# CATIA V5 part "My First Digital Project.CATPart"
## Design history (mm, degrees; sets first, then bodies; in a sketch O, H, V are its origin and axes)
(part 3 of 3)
Set68 "IFC Single Panel"
  Set69 "Construction Geometry"
    UdfFeature26 "Insertion Axis": UdfInputSpec1 {plane2lines}, UdfInputSpec3 Project20, UdfInputSpec4 Project21, UdfInputSpec5 Project22, UdfComponents Set72, UdfOutputs AxisSystem42
    AxisSystem39 "Insertion Axis Clone": origin (14674.5386, 9859.6746, 133.35), X (0.2658, 0.964, 0), Y (-0.964, 0.2658, 0), Z (0, 0, 1)
    AxisSystem40 "Lining Axis": origin (14637.8088, 9869.8004, 133.35), X (0.2658, 0.964, 0), Y (-0.964, 0.2658, 0), Z (0, 0, 1)
    AxisSystem41 "Panel Axis": origin (14673.4799, 9879.7271, 152.4), X (0.2658, 0.964, 0), Y (-0.964, 0.2658, 0), Z (0, 0, 1)
    UdfFeature27 "Middle": UdfInputSpec1 {pointcoord X 0, Y 0, Z 0, RefAxis AxisSystem40}, UdfInputSpec2 {pointcoord X 526.9992 {= `UdfFeature27.Window Width` /2}, Y 0, Z 0, RefAxis AxisSystem40}, UdfInputSpec3 {pointcoord X 1053.9984 {= `UdfFeature27.Window Width`}, Y 0, Z 0, RefAxis AxisSystem40}, UdfComponents Set73, UdfOutputs Point212
  Set70 "Window Lining"
    Sketch17 "Opening Contour" on edge [XY plane of AxisSystem40 | ZX plane of AxisSystem40], origin (14637.8088, 9869.8004, 133.35), H (0.2658, 0.964, 0), V (0, 0, 1)
      line L1 (0, 0) -> (1053.9984, 0)
      line L2 (1053.9984, 0) -> (1053.9984, 2324.1)
      line L3 (1053.9984, 2324.1) -> (0, 2324.1)
      line L4 (0, 2324.1) -> (0, 0)
      length L4 = 2324.1
      length L3 = 1053.9984
      horizontal: L1 H, L3 H
      vertical: L2 V, L4 V
    Body36 "Lining"
      Pad8: profile Sketch17, direction (0.964, -0.2658, 0), length 38.1, mirrored extent, thin wall 19.05
  Set71 "Window Panel"
    Body37 "Panel"
      UdfFeature28 "IFC Window Panel": UdfInputSpec10 edge [ZX plane of AxisSystem41 | YZ plane of AxisSystem41], UdfInputSpec1 {pointcoord X 1015.8984 {= `External.Rotate Axis Offset`}, Y 0, Z 0, RefPoint vertex [YZ plane of AxisSystem41 | ZX plane of AxisSystem41 | XY plane of AxisSystem41], RefAxis AxisSystem41}, UdfInputSpec3 edge [ZX plane of AxisSystem41 | YZ plane of AxisSystem41], UdfInputSpec4 {pointcoord X 0, Y 0, Z 1015.8984 {= `External.Rotate Axis Offset`}, RefPoint vertex [YZ plane of AxisSystem41 | ZX plane of AxisSystem41 | XY plane of AxisSystem41], RefAxis AxisSystem41}, UdfComponents a sketch, UdfInputSpec6 edge [XY plane of AxisSystem41 | ZX plane of AxisSystem41], UdfInputSpec7 {pointcoord X 0 {= `External.X Translate`}, Y 0, Z 0 {= `External.Z Translate`}, RefPoint vertex [YZ plane of AxisSystem41 | ZX plane of AxisSystem41 | XY plane of AxisSystem41], RefAxis AxisSystem41}, UdfInputSpec9 edge [XY plane of AxisSystem41 | ZX plane of AxisSystem41], OperationType "SideHungRightHand", Open Ratio 0
Set72 "Insertion Geometry"
  Plane19 "Construction Plane": type 2Lines
  Project20 "Insertion Point clone": Support Plane19
  Project21 "Insertion Line Clone": Support Plane19
  Project22 "Orientation Line Clone": Support Plane19
  Line84 "X Direction": type Normal, RefPoint Project20, RefSkin Plane19, Start 0, End 1
  AxisSystem42 "Insertion Axis": origin (14674.5386, 9859.6746, 133.35), X (0.2658, 0.964, 0), Y (-0.964, 0.2658, 0), Z (0, 0, 1)
Set73 "UDF Geometry"
  Point211 "Left": (0, 0, 0), in AxisSystem40
  Point212 "Middle": (526.9992 {= `UdfFeature27.Window Width` /2}, 0, 0), in AxisSystem40
  Point213 "Right": (1053.9984 {= `UdfFeature27.Window Width`}, 0, 0), in AxisSystem40
Set74 "UDF Geometry"
  Line85 "V Rotation Axis": type PtDir, RefPoint {point type Coord, X 1015.8984 {= `External.Rotate Axis Offset`}, Y 0, Z 0, RefPoint vertex [YZ plane of AxisSystem41 | ZX plane of AxisSystem41 | XY plane of AxisSystem41], RefAxis AxisSystem41}, Direction edge [ZX plane of AxisSystem41 | YZ plane of AxisSystem41], Start 0, End 304.8
  Line86 "H Rotation Axis": type PtDir, RefPoint {point type Coord, X 0, Y 0, Z 1015.8984 {= `External.Rotate Axis Offset`}, RefPoint vertex [YZ plane of AxisSystem41 | ZX plane of AxisSystem41 | XY plane of AxisSystem41], RefAxis AxisSystem41}, Direction edge [XY plane of AxisSystem41 | ZX plane of AxisSystem41], Start 0, End 304.8
  Point214 "Translate Point": (0 {= `External.X Translate`}, 0, 0 {= `External.Z Translate`}), relative to vertex [YZ plane of AxisSystem41 | ZX plane of AxisSystem41 | XY plane of AxisSystem41], in AxisSystem41
  Line87 "Trans X Axis": type PtDir, RefPoint Point214, Direction edge [XY plane of AxisSystem41 | ZX plane of AxisSystem41], Start 0, End 304.8
  Line88 "Trans ZAxis": type PtDir, RefPoint Point214, Direction edge [ZX plane of AxisSystem41 | YZ plane of AxisSystem41], Start 0, End 304.8
  Rotate29 "Rotate Horizontal Point": ToTransfor Point214, Axis Line86, Angle 0 {= `External.Open Angle`}
  Rotate30 "Rotate Horizontal Z Axis": ToTransfor Line88, Axis Line86, Angle 0 {= `External.Open Angle`}
  Rotate31 "Rotate Vertical Point": ToTransfor Point214, Axis Line85, Angle 0 {= `External.Open Angle`}
  Rotate32 "Rotate Vertical X Axis": ToTransfor Line87, Axis Line85, Angle 0 {= `External.Open Angle`}
  Line89 "X Direction": stored without definition
  Line90 "Z Direction": stored without definition
  Point215 "Origin": stored without definition
  Plane20: type Normal, Curve Line90, RefPoint Point215
  Line91 "Y Direction": type Angle, RefPoint Point215, Curve Line89, Support Plane20, Start 0, End 304.8, Angle 90
  AxisSystem43 "Window Open Axis": origin (14673.4799, 9879.7271, 152.4), X (0.2658, 0.964, 0), Y (-0.964, 0.2658, 0), Z (0, 0, 1)
Set75 "UDF Geometry"
  Point216 "B-L": (25.4 {= UdfFeature28.FrameThickness}, 0, 25.4 {= UdfFeature28.FrameThickness}), relative to vertex [YZ plane of UdfFeature28 | ZX plane of UdfFeature28 | XY plane of UdfFeature28], in 
  Point217 "B": (507.9492 {= `UdfFeature28.Panel Width` /2}, 0, 25.4 {= UdfFeature28.FrameThickness}), relative to vertex [YZ plane of UdfFeature28 | ZX plane of UdfFeature28 | XY plane of UdfFeature28], in 
  Point218 "B-R": (990.4984 {= `UdfFeature28.Panel Width` -UdfFeature28.FrameThickness}, 0, 25.4 {= UdfFeature28.FrameThickness}), relative to vertex [YZ plane of UdfFeature28 | ZX plane of UdfFeature28 | XY plane of UdfFeature28], in 
  Point219 "R": (990.4984 {= Point218.X}, 0, 1143 {= `UdfFeature28.Panel Height` /2}), relative to vertex [YZ plane of UdfFeature28 | ZX plane of UdfFeature28 | XY plane of UdfFeature28], in 
  Point220 "T-R": (990.4984 {= Point218.X}, 0, 2260.6 {= `UdfFeature28.Panel Height` -UdfFeature28.FrameThickness}), relative to vertex [YZ plane of UdfFeature28 | ZX plane of UdfFeature28 | XY plane of UdfFeature28], in 
  Point221 "T": (507.9492 {= Point217.X}, 0, 2260.6 {= Point220.Z}), relative to vertex [YZ plane of UdfFeature28 | ZX plane of UdfFeature28 | XY plane of UdfFeature28], in 
  Point222 "T-L": (25.4 {= Point216.X}, 0, 2260.6 {= Point220.Z}), relative to vertex [YZ plane of UdfFeature28 | ZX plane of UdfFeature28 | XY plane of UdfFeature28], in 
  Point223 "L": (25.4 {= Point216.X}, 0, 1143 {= Point219.Z}), relative to vertex [YZ plane of UdfFeature28 | ZX plane of UdfFeature28 | XY plane of UdfFeature28], in 
  Point224 "C": (507.9492 {= `UdfFeature28.Panel Width` /2}, 0, 1143 {= `UdfFeature28.Panel Height` /2}), relative to vertex [YZ plane of UdfFeature28 | ZX plane of UdfFeature28 | XY plane of UdfFeature28], in 
  Point225 "B2": (0, 0, 76.2), relative to Point217, in 
  Point226 "T2": (0, 0, -76.2), relative to Point221, in 
  Point227 "L2": (76.2, 0, 0), relative to Point223, in 
  Point228 "R2": (-76.2, 0, 0), relative to Point219, in 
  Point229 "L3": (-253.9746 {= -`UdfFeature28.Panel Width` /4}, 0, 0), relative to Point224, in 
  Point230 "R3": (253.9746 {= -Point229.X}, 0, 0), relative to Point224, in 
  Point231 "T3": (0, 0, 571.5 {= `UdfFeature28.Panel Height` /4}), relative to Point224, in 
  Point232 "B3": (0, 0, -571.5 {= - Point231.Z}), relative to Point224, in 
  LineCorner79 "Left": Elements (Point222; Point219; Point216)
  LineCorner80 "Right": Elements (Point220; Point223; Point218)
  LineCorner81 "Top": Elements (Point222; Point217; Point220)
  LineCorner82 "Bottom": Elements (Point216; Point221; Point218)
  Join36 "Left and Bottom": Elements (LineCorner79; LineCorner82)
  Join37 "Right and Bottom": Elements (LineCorner80; LineCorner82)
  LineCorner83 "Pivot H Top": Elements (Point227; Point223; Point221; Point219; Point228)
  LineCorner84 "Pivot H Bottom": Elements (Point223; Point217; Point219)
  Join38 "Pivot H": Elements (LineCorner83; LineCorner84)
  LineCorner85 "Pivot V Left": Elements (Point226; Point221; Point223; Point217; Point225)
  LineCorner86 "Pivot V Right": Elements (Point221; Point219; Point217)
  Join39 "Pivot V": Elements (LineCorner85; LineCorner86)
  Line92 "Sliding H": type PtPt, FirstPoint Point229, SecondPoint Point230
  Line93 "Sliding V": type PtPt, FirstPoint Point231, SecondPoint Point232
  Point233: (25.4 {= UdfFeature28.FrameThickness}, 0, 0), relative to Point216, in 
  Point234: (-25.4 {= -UdfFeature28.FrameThickness}, 0, 25.4 {= UdfFeature28.FrameThickness}), relative to Point218, in 
  Point235: (25.4 {= UdfFeature28.FrameThickness}, 0, -25.4 {= -UdfFeature28.FrameThickness}), relative to Point222, in 
  Point236: (-25.4 {= -UdfFeature28.FrameThickness}, 0, 0), relative to Point220, in 
  Point237: (0, 0, -25.4 {= -UdfFeature28.FrameThickness}), relative to Point220, in 
  Point238: (0, 0, 25.4 {= UdfFeature28.FrameThickness}), relative to Point216, in 
  LineCorner87 "Removable-1": Elements (Point222; Point236; Point234; Point238)
  LineCorner88 "Removable-2": Elements (Point235; Point237; Point218; Point233)
  Line94 "Removable-3": type PtPt, FirstPoint Point237, SecondPoint Point233
  Join40 "Removable": Elements (LineCorner87; LineCorner88; Line94)
  LineCorner89 "Fixed": Elements (Point222; Point220; Point218; Point216)
  DatumCurve8 "OperationSymbol"
Body38 "Opening Volume Body"
  GTCArcGeoOpnVolume9 "Opening Volume"
Set76 "IFC Single Panel"
  Set77 "Construction Geometry"
    UdfFeature29 "Insertion Axis": UdfInputSpec1 {plane2lines}, UdfInputSpec3 Project23, UdfInputSpec4 Project24, UdfInputSpec5 Project25, UdfComponents Set80, UdfOutputs AxisSystem47
    AxisSystem44 "Insertion Axis Clone": origin (14991.6842, 11036.8997, 133.35), X (0.1815, 0.9834, 0), Y (-0.9834, 0.1815, 0), Z (0, 0, 1)
    AxisSystem45 "Lining Axis": origin (14954.2167, 11043.8131, 133.35), X (0.1815, 0.9834, 0), Y (-0.9834, 0.1815, 0), Z (0, 0, 1)
    AxisSystem46 "Panel Axis": origin (14988.8963, 11056.7857, 152.4), X (0.1815, 0.9834, 0), Y (-0.9834, 0.1815, 0), Z (0, 0, 1)
    UdfFeature30 "Middle": UdfInputSpec1 {pointcoord X 0, Y 0, Z 0, RefAxis AxisSystem45}, UdfInputSpec2 {pointcoord X 526.9992 {= `UdfFeature30.Window Width` /2}, Y 0, Z 0, RefAxis AxisSystem45}, UdfInputSpec3 {pointcoord X 1053.9984 {= `UdfFeature30.Window Width`}, Y 0, Z 0, RefAxis AxisSystem45}, UdfComponents Set81, UdfOutputs Point240
  Set78 "Window Lining"
    Sketch18 "Opening Contour" on edge [XY plane of AxisSystem45 | ZX plane of AxisSystem45], origin (14954.2167, 11043.8131, 133.35), H (0.1815, 0.9834, 0), V (0, 0, 1)
      line L1 (0, 0) -> (1053.9984, 0)
      line L2 (1053.9984, 0) -> (1053.9984, 2324.1)
      line L3 (1053.9984, 2324.1) -> (0, 2324.1)
      line L4 (0, 2324.1) -> (0, 0)
      length L4 = 2324.1
      length L3 = 1053.9984
      horizontal: L1 H, L3 H
      vertical: L2 V, L4 V
    Body39 "Lining"
      Pad9: profile Sketch18, direction (0.9834, -0.1815, 0), length 38.1, mirrored extent, thin wall 19.05
  Set79 "Window Panel"
    Body40 "Panel"
      UdfFeature31 "IFC Window Panel": UdfInputSpec10 edge [ZX plane of AxisSystem46 | YZ plane of AxisSystem46], UdfInputSpec1 {pointcoord X 1015.8984 {= `External.Rotate Axis Offset`}, Y 0, Z 0, RefPoint vertex [YZ plane of AxisSystem46 | ZX plane of AxisSystem46 | XY plane of AxisSystem46], RefAxis AxisSystem46}, UdfInputSpec3 edge [ZX plane of AxisSystem46 | YZ plane of AxisSystem46], UdfInputSpec4 {pointcoord X 0, Y 0, Z 1015.8984 {= `External.Rotate Axis Offset`}, RefPoint vertex [YZ plane of AxisSystem46 | ZX plane of AxisSystem46 | XY plane of AxisSystem46], RefAxis AxisSystem46}, UdfComponents a sketch, UdfInputSpec6 edge [XY plane of AxisSystem46 | ZX plane of AxisSystem46], UdfInputSpec7 {pointcoord X 0 {= `External.X Translate`}, Y 0, Z 0 {= `External.Z Translate`}, RefPoint vertex [YZ plane of AxisSystem46 | ZX plane of AxisSystem46 | XY plane of AxisSystem46], RefAxis AxisSystem46}, UdfInputSpec9 edge [XY plane of AxisSystem46 | ZX plane of AxisSystem46], OperationType "SideHungRightHand", Open Ratio 0
Set80 "Insertion Geometry"
  Plane21 "Construction Plane": type 2Lines
  Project23 "Insertion Point clone": Support Plane21
  Project24 "Insertion Line Clone": Support Plane21
  Project25 "Orientation Line Clone": Support Plane21
  Line95 "X Direction": type Normal, RefPoint Project23, RefSkin Plane21, Start 0, End 1
  AxisSystem47 "Insertion Axis": origin (14991.6842, 11036.8997, 133.35), X (0.1815, 0.9834, 0), Y (-0.9834, 0.1815, 0), Z (0, 0, 1)
Set81 "UDF Geometry"
  Point239 "Left": (0, 0, 0), in AxisSystem45
  Point240 "Middle": (526.9992 {= `UdfFeature30.Window Width` /2}, 0, 0), in AxisSystem45
  Point241 "Right": (1053.9984 {= `UdfFeature30.Window Width`}, 0, 0), in AxisSystem45
Set82 "UDF Geometry"
  Line96 "V Rotation Axis": type PtDir, RefPoint {point type Coord, X 1015.8984 {= `External.Rotate Axis Offset`}, Y 0, Z 0, RefPoint vertex [YZ plane of AxisSystem46 | ZX plane of AxisSystem46 | XY plane of AxisSystem46], RefAxis AxisSystem46}, Direction edge [ZX plane of AxisSystem46 | YZ plane of AxisSystem46], Start 0, End 304.8
  Line97 "H Rotation Axis": type PtDir, RefPoint {point type Coord, X 0, Y 0, Z 1015.8984 {= `External.Rotate Axis Offset`}, RefPoint vertex [YZ plane of AxisSystem46 | ZX plane of AxisSystem46 | XY plane of AxisSystem46], RefAxis AxisSystem46}, Direction edge [XY plane of AxisSystem46 | ZX plane of AxisSystem46], Start 0, End 304.8
  Point242 "Translate Point": (0 {= `External.X Translate`}, 0, 0 {= `External.Z Translate`}), relative to vertex [YZ plane of AxisSystem46 | ZX plane of AxisSystem46 | XY plane of AxisSystem46], in AxisSystem46
  Line98 "Trans X Axis": type PtDir, RefPoint Point242, Direction edge [XY plane of AxisSystem46 | ZX plane of AxisSystem46], Start 0, End 304.8
  Line99 "Trans ZAxis": type PtDir, RefPoint Point242, Direction edge [ZX plane of AxisSystem46 | YZ plane of AxisSystem46], Start 0, End 304.8
  Rotate33 "Rotate Horizontal Point": ToTransfor Point242, Axis Line97, Angle 0 {= `External.Open Angle`}
  Rotate34 "Rotate Horizontal Z Axis": ToTransfor Line99, Axis Line97, Angle 0 {= `External.Open Angle`}
  Rotate35 "Rotate Vertical Point": ToTransfor Point242, Axis Line96, Angle 0 {= `External.Open Angle`}
  Rotate36 "Rotate Vertical X Axis": ToTransfor Line98, Axis Line96, Angle 0 {= `External.Open Angle`}
  Line100 "X Direction": stored without definition
  Line101 "Z Direction": stored without definition
  Point243 "Origin": stored without definition
  Plane22: type Normal, Curve Line101, RefPoint Point243
  Line102 "Y Direction": type Angle, RefPoint Point243, Curve Line100, Support Plane22, Start 0, End 304.8, Angle 90
  AxisSystem48 "Window Open Axis": origin (14988.8963, 11056.7857, 152.4), X (0.1815, 0.9834, 0), Y (-0.9834, 0.1815, 0), Z (0, 0, 1)
Set83 "UDF Geometry"
  Point244 "B-L": (25.4 {= UdfFeature31.FrameThickness}, 0, 25.4 {= UdfFeature31.FrameThickness}), relative to vertex [YZ plane of UdfFeature31 | ZX plane of UdfFeature31 | XY plane of UdfFeature31], in 
  Point245 "B": (507.9492 {= `UdfFeature31.Panel Width` /2}, 0, 25.4 {= UdfFeature31.FrameThickness}), relative to vertex [YZ plane of UdfFeature31 | ZX plane of UdfFeature31 | XY plane of UdfFeature31], in 
  Point246 "B-R": (990.4984 {= `UdfFeature31.Panel Width` -UdfFeature31.FrameThickness}, 0, 25.4 {= UdfFeature31.FrameThickness}), relative to vertex [YZ plane of UdfFeature31 | ZX plane of UdfFeature31 | XY plane of UdfFeature31], in 
  Point247 "R": (990.4984 {= Point246.X}, 0, 1143 {= `UdfFeature31.Panel Height` /2}), relative to vertex [YZ plane of UdfFeature31 | ZX plane of UdfFeature31 | XY plane of UdfFeature31], in 
  Point248 "T-R": (990.4984 {= Point246.X}, 0, 2260.6 {= `UdfFeature31.Panel Height` -UdfFeature31.FrameThickness}), relative to vertex [YZ plane of UdfFeature31 | ZX plane of UdfFeature31 | XY plane of UdfFeature31], in 
  Point249 "T": (507.9492 {= Point245.X}, 0, 2260.6 {= Point248.Z}), relative to vertex [YZ plane of UdfFeature31 | ZX plane of UdfFeature31 | XY plane of UdfFeature31], in 
  Point250 "T-L": (25.4 {= Point244.X}, 0, 2260.6 {= Point248.Z}), relative to vertex [YZ plane of UdfFeature31 | ZX plane of UdfFeature31 | XY plane of UdfFeature31], in 
  Point251 "L": (25.4 {= Point244.X}, 0, 1143 {= Point247.Z}), relative to vertex [YZ plane of UdfFeature31 | ZX plane of UdfFeature31 | XY plane of UdfFeature31], in 
  Point252 "C": (507.9492 {= `UdfFeature31.Panel Width` /2}, 0, 1143 {= `UdfFeature31.Panel Height` /2}), relative to vertex [YZ plane of UdfFeature31 | ZX plane of UdfFeature31 | XY plane of UdfFeature31], in 
  Point253 "B2": (0, 0, 76.2), relative to Point245, in 
  Point254 "T2": (0, 0, -76.2), relative to Point249, in 
  Point255 "L2": (76.2, 0, 0), relative to Point251, in 
  Point256 "R2": (-76.2, 0, 0), relative to Point247, in 
  Point257 "L3": (-253.9746 {= -`UdfFeature31.Panel Width` /4}, 0, 0), relative to Point252, in 
  Point258 "R3": (253.9746 {= -Point257.X}, 0, 0), relative to Point252, in 
  Point259 "T3": (0, 0, 571.5 {= `UdfFeature31.Panel Height` /4}), relative to Point252, in 
  Point260 "B3": (0, 0, -571.5 {= - Point259.Z}), relative to Point252, in 
  LineCorner90 "Left": Elements (Point250; Point247; Point244)
  LineCorner91 "Right": Elements (Point248; Point251; Point246)
  LineCorner92 "Top": Elements (Point250; Point245; Point248)
  LineCorner93 "Bottom": Elements (Point244; Point249; Point246)
  Join41 "Left and Bottom": Elements (LineCorner90; LineCorner93)
  Join42 "Right and Bottom": Elements (LineCorner91; LineCorner93)
  LineCorner94 "Pivot H Top": Elements (Point255; Point251; Point249; Point247; Point256)
  LineCorner95 "Pivot H Bottom": Elements (Point251; Point245; Point247)
  Join43 "Pivot H": Elements (LineCorner94; LineCorner95)
  LineCorner96 "Pivot V Left": Elements (Point254; Point249; Point251; Point245; Point253)
  LineCorner97 "Pivot V Right": Elements (Point249; Point247; Point245)
  Join44 "Pivot V": Elements (LineCorner96; LineCorner97)
  Line103 "Sliding H": type PtPt, FirstPoint Point257, SecondPoint Point258
  Line104 "Sliding V": type PtPt, FirstPoint Point259, SecondPoint Point260
  Point261: (25.4 {= UdfFeature31.FrameThickness}, 0, 0), relative to Point244, in 
  Point262: (-25.4 {= -UdfFeature31.FrameThickness}, 0, 25.4 {= UdfFeature31.FrameThickness}), relative to Point246, in 
  Point263: (25.4 {= UdfFeature31.FrameThickness}, 0, -25.4 {= -UdfFeature31.FrameThickness}), relative to Point250, in 
  Point264: (-25.4 {= -UdfFeature31.FrameThickness}, 0, 0), relative to Point248, in 
  Point265: (0, 0, -25.4 {= -UdfFeature31.FrameThickness}), relative to Point248, in 
  Point266: (0, 0, 25.4 {= UdfFeature31.FrameThickness}), relative to Point244, in 
  LineCorner98 "Removable-1": Elements (Point250; Point264; Point262; Point266)
  LineCorner99 "Removable-2": Elements (Point263; Point265; Point246; Point261)
  Line105 "Removable-3": type PtPt, FirstPoint Point265, SecondPoint Point261
  Join45 "Removable": Elements (LineCorner98; LineCorner99; Line105)
  LineCorner100 "Fixed": Elements (Point250; Point248; Point246; Point244)
  DatumCurve9 "OperationSymbol"
Body41 "Structural Solid Body", material "Brushed metal 2"
  GTCArcMemberStrSolidRes1 "Structural Solid": OuterPerimeter 2021.7141, X-SectionArea 0.0203684
Body42 "Structural Solid Body", material "Brushed metal 2"
  GTCArcMemberStrSolidRes2 "Structural Solid": OuterPerimeter 2021.7141, X-SectionArea 0.0203684
Body43 "Structural Solid Body", material "Brushed metal 2"
  GTCArcMemberStrSolidRes3 "Structural Solid": OuterPerimeter 2021.7141, X-SectionArea 0.0203684
Body44 "Structural Solid Body", material "Brushed metal 2"
  GTCArcMemberStrSolidRes4 "Structural Solid": OuterPerimeter 2021.7141, X-SectionArea 0.0203684
Body45 "Structural Solid Body", material "Brushed metal 2"
  GTCArcMemberStrSolidRes5 "Structural Solid": OuterPerimeter 1282.3325, X-SectionArea 0.0086417
Body46 "Structural Solid Body", material "Brushed metal 2"
  GTCArcMemberStrSolidRes6 "Structural Solid": OuterPerimeter 1282.3325, X-SectionArea 0.0086417
Body47 "Structural Solid Body", material "Brushed metal 2"
  GTCArcMemberStrSolidRes7 "Structural Solid": OuterPerimeter 1282.3325, X-SectionArea 0.0086417
Body48 "Structural Solid Body", material "Brushed metal 2"
  GTCArcMemberStrSolidRes8 "Structural Solid": OuterPerimeter 1282.3325, X-SectionArea 0.0086417
Body49 "Structural Solid Body", material "Brushed metal 2"
  GTCArcMemberStrSolidRes9 "Structural Solid": OuterPerimeter 1282.3325, X-SectionArea 0.0086417
Body50 "Structural Solid Body", material "Brushed metal 2"
  GTCArcMemberStrSolidRes10 "Structural Solid": OuterPerimeter 1282.3325, X-SectionArea 0.0086417
Body51 "Structural Solid Body", material "Brushed metal 2"
  GTCArcMemberStrSolidRes11 "Structural Solid": OuterPerimeter 1282.3325, X-SectionArea 0.0086417
Body52 "Structural Solid Body", material "Brushed metal 2"
  GTCArcMemberStrSolidRes12 "Structural Solid": OuterPerimeter 1282.3325, X-SectionArea 0.0086417
Body53 "Structural Solid Body", material "Brushed metal 2"
  GTCArcMemberStrSolidRes13 "Structural Solid": OuterPerimeter 1282.3325, X-SectionArea 0.0086417
Body54 "Structural Solid Body", material "Brushed metal 2"
  GTCArcMemberStrSolidRes14 "Structural Solid": OuterPerimeter 1282.3325, X-SectionArea 0.0086417
Body55 "Structural Solid Body", material "Brushed metal 2"
  GTCArcMemberStrSolidRes15 "Structural Solid": OuterPerimeter 1282.3325, X-SectionArea 0.0086417
Body56 "Structural Solid Body", material "Brushed metal 2"
  GTCArcMemberStrSolidRes16 "Structural Solid": OuterPerimeter 1282.3325, X-SectionArea 0.0086417
Body57 "Structural Solid Body", material "Brushed metal 2"
  GTCArcMemberStrSolidRes17 "Structural Solid": OuterPerimeter 1282.3325, X-SectionArea 0.0086417
Body58 "Structural Solid Body", material "Brushed metal 2"
  GTCArcMemberStrSolidRes18 "Structural Solid": OuterPerimeter 1282.3325, X-SectionArea 0.0086417
Set84 "Construction Geometry"
  Plane23: type Angle, Direction edge of LineCorner1, Angle 20
Body59 "Structural Solid Body", material "Wall of Castle"
  GTCArcStrWallSolidRes1 "Structural Solid": NominalLength 2982.2443, GrossFootPrintArea 0.908988, NetFootPrintArea 0.908988, GrossVolume 1.6879
Body60 "Structural Solid Body", material "Wall of Castle"
  GTCArcStrWallSolidRes2 "Structural Solid": NominalLength 2637.4386, GrossFootPrintArea 0.803891, NetFootPrintArea 0.803891, GrossVolume 1.49287
Set85 "Construction Geometry"
  Plane24: type Angle, Direction edge of LineCorner1, Angle 20
Body61 "Structural Solid Body", material "Wall of Castle"
  GTCArcStrWallSolidRes3 "Structural Solid": NominalLength 2637.4386, GrossFootPrintArea 0.803891, NetFootPrintArea 0.803891, GrossVolume 1.49287
Set86 "Construction Geometry"
  Plane25: type Angle, Direction edge of LineCorner1, Angle 20
Body62 "Structural Solid Body", material "Wall of Castle"
  GTCArcStrWallSolidRes4 "Structural Solid": NominalLength 2982.2443, GrossFootPrintArea 0.908988, NetFootPrintArea 0.908988, GrossVolume 1.6879
Set87 "Construction Geometry"
  Plane26: type Angle, Direction edge of LineCorner1, Angle 20
Body63 "Structural Solid Body", material "Steel"
  GTCArcMemberStrSolidRes19 "Structural Solid": OuterPerimeter 478.7787, X-SectionArea 0.0182415
Body64 "Structural Solid Body", material "Steel"
  GTCArcMemberStrSolidRes20 "Structural Solid": OuterPerimeter 478.7787, X-SectionArea 0.0182415
Body65 "Structural Solid Body", material "Steel"
  GTCArcMemberStrSolidRes21 "Structural Solid": OuterPerimeter 478.7787, X-SectionArea 0.0182415
Body66 "Structural Solid Body", material "Steel"
  GTCArcMemberStrSolidRes22 "Structural Solid": OuterPerimeter 478.7787, X-SectionArea 0.0182415
Body67 "Structural Solid Body", material "Steel"
  GTCArcMemberStrSolidRes23 "Structural Solid": OuterPerimeter 478.7787, X-SectionArea 0.0182415
Body68 "Structural Solid Body", material "Steel"
  GTCArcMemberStrSolidRes24 "Structural Solid": OuterPerimeter 478.7787, X-SectionArea 0.0182415
Body69 "Structural Solid Body", material "Steel"
  GTCArcMemberStrSolidRes25 "Structural Solid": OuterPerimeter 478.7787, X-SectionArea 0.0182415
Body70 "Structural Solid Body", material "Steel"
  GTCArcMemberStrSolidRes26 "Structural Solid": OuterPerimeter 478.7787, X-SectionArea 0.0182415
Relations
  `Sill-Top` = `Sill-Right`
  `Sill-Left` = `Sill-Right`
  `GTCArcWall1.H-Offset` = 0mm
  `GTCArcWall1.V-Offset` = 0mm
  `Sill-Top` = `Sill-Right`
  `Sill-Left` = `Sill-Right`
  `GTCArcWall1.H-Offset` = 0mm
  `GTCArcWall1.V-Offset` = 0mm
  `Sill-Top` = `Sill-Right`
  `Sill-Left` = `Sill-Right`
  `Sill-Right` = `Sill-Bottom`
  rule "Dimension Rule":
    /*Rule created by alan 9/27/2006*/
    `External.Open Angle` = 0deg
    `External.Rotate Axis Offset` =0ft
    `External.X Translate` = 0ft
    `External.Z Translate` = 0ft
    External.Vertical =true
    if External.OperationType  == "SideHungRightHand"
    {  `External.Rotate Axis Offset`  = `External.Panel Width`
    	`External.Open Angle` =- PI/2*`External.Open Ratio`
    }
    if External.OperationType  == "SideHungLeftHand"
    {   `External.Open Angle` =  PI/2*`External.Open Ratio`
    }
    if External.OperationType  == "TiltAndTurnRightHand"
    {    `External.Rotate Axis Offset`  = `External.Panel Width`
    	`External.Open Angle` = -PI/2*`External.Open Ratio`
    }
    if External.OperationType  == "TiltAndTurnLeftHand"
    {   `External.Open Angle` = PI/2*`External.Open Ratio`
    }
    if External.OperationType  == "TopHung"
    {  `External.Rotate Axis Offset` =`External.Panel Height`
    	`External.Open Angle` = PI/2*`External.Open Ratio`
    	External.Vertical = false
    }
    if External.OperationType  == "BottomHung"
    {   `External.Open Angle` = -PI/2*`External.Open Ratio`
    	External.Vertical = false
    }
    if External.OperationType  == "PivotVertical"
    {   `External.Open Angle` = PI/2*`External.Open Ratio`
    	`External.Rotate Axis Offset` =`External.Panel Width` /2
    }
    if External.OperationType  == "PivotHorizontal"
    {   `External.Open Angle` = PI/2*`External.Open Ratio`
    	`External.Rotate Axis Offset` =`External.Panel Height` /2
    	External.Vertical = false
    }
    if External.OperationType  == "SlidingHorizontal"
    {  `External.X Translate` = `External.Panel Width` * `External.Open Ratio`
    }
    if External.OperationType  == "SlidingVertical"
    {   `External.Z Translate` = `External.Panel Height`  * `External.Open Ratio`
    }
  rule "Rotation Rule":
    /*Rule created by alan 9/27/2006*/
    if External.Vertical==true
    {Line14 = Rotate4
    	Line15 =Line13
    Point25 =Rotate3 }
    else
    {Line14 =Line12
    	Line15 =Rotate2
    Point25 =Rotate1 }
  `GTCArcWall1.H-Offset` = 0mm
  `GTCArcWall1.V-Offset` = `Sill-Bottom`
  `Sill-Top` = `Sill-Right`
  `Sill-Left` = `Sill-Right`
  `Sill-Right` = `Sill-Bottom`
  `GTCArcWall1.H-Offset` = 0mm
  `GTCArcWall1.V-Offset` = `Sill-Bottom`
  rule "Dimension Rule":
    /*Rule created by alan 9/27/2006*/
    `External.Open Angle` = 0deg
    `External.Rotate Axis Offset` =0ft
    `External.X Translate` = 0ft
    `External.Z Translate` = 0ft
    External.Vertical =true
    if External.OperationType  == "SideHungRightHand"
    {  `External.Rotate Axis Offset`  = `External.Panel Width`
    	`External.Open Angle` =- PI/2*`External.Open Ratio`
    }
    if External.OperationType  == "SideHungLeftHand"
    {   `External.Open Angle` =  PI/2*`External.Open Ratio`
    }
    if External.OperationType  == "TiltAndTurnRightHand"
    {    `External.Rotate Axis Offset`  = `External.Panel Width`
    	`External.Open Angle` = -PI/2*`External.Open Ratio`
    }
    if External.OperationType  == "TiltAndTurnLeftHand"
    {   `External.Open Angle` = PI/2*`External.Open Ratio`
    }
    if External.OperationType  == "TopHung"
    {  `External.Rotate Axis Offset` =`External.Panel Height`
    	`External.Open Angle` = PI/2*`External.Open Ratio`
    	External.Vertical = false
    }
    if External.OperationType  == "BottomHung"
    {   `External.Open Angle` = -PI/2*`External.Open Ratio`
    	External.Vertical = false
    }
    if External.OperationType  == "PivotVertical"
    {   `External.Open Angle` = PI/2*`External.Open Ratio`
    	`External.Rotate Axis Offset` =`External.Panel Width` /2
    }
    if External.OperationType  == "PivotHorizontal"
    {   `External.Open Angle` = PI/2*`External.Open Ratio`
    	`External.Rotate Axis Offset` =`External.Panel Height` /2
    	External.Vertical = false
    }
    if External.OperationType  == "SlidingHorizontal"
    {  `External.X Translate` = `External.Panel Width` * `External.Open Ratio`
    }
    if External.OperationType  == "SlidingVertical"
    {   `External.Z Translate` = `External.Panel Height`  * `External.Open Ratio`
    }
  rule "Rotation Rule":
    /*Rule created by alan 9/27/2006*/
    if External.Vertical==true
    {Line25 = Rotate8
    	Line26 =Line24
    Point53 =Rotate7 }
    else
    {Line25 =Line23
    	Line26 =Rotate6
    Point53 =Rotate5 }
  `Sill-Top` = `Sill-Right`
  `Sill-Left` = `Sill-Right`
  `Sill-Right` = `Sill-Bottom`
  rule "Dimension Rule":
    /*Rule created by alan 9/27/2006*/
    `External.Open Angle` = 0deg
    `External.Rotate Axis Offset` =0ft
    `External.X Translate` = 0ft
    `External.Z Translate` = 0ft
    External.Vertical =true
    if External.OperationType  == "SideHungRightHand"
    {  `External.Rotate Axis Offset`  = `External.Panel Width`
    	`External.Open Angle` =- PI/2*`External.Open Ratio`
    }
    if External.OperationType  == "SideHungLeftHand"
    {   `External.Open Angle` =  PI/2*`External.Open Ratio`
    }
    if External.OperationType  == "TiltAndTurnRightHand"
    {    `External.Rotate Axis Offset`  = `External.Panel Width`
    	`External.Open Angle` = -PI/2*`External.Open Ratio`
    }
    if External.OperationType  == "TiltAndTurnLeftHand"
    {   `External.Open Angle` = PI/2*`External.Open Ratio`
    }
    if External.OperationType  == "TopHung"
    {  `External.Rotate Axis Offset` =`External.Panel Height`
    	`External.Open Angle` = PI/2*`External.Open Ratio`
    	External.Vertical = false
    }
    if External.OperationType  == "BottomHung"
    {   `External.Open Angle` = -PI/2*`External.Open Ratio`
    	External.Vertical = false
    }
    if External.OperationType  == "PivotVertical"
    {   `External.Open Angle` = PI/2*`External.Open Ratio`
    	`External.Rotate Axis Offset` =`External.Panel Width` /2
    }
    if External.OperationType  == "PivotHorizontal"
    {   `External.Open Angle` = PI/2*`External.Open Ratio`
    	`External.Rotate Axis Offset` =`External.Panel Height` /2
    	External.Vertical = false
    }
    if External.OperationType  == "SlidingHorizontal"
    {  `External.X Translate` = `External.Panel Width` * `External.Open Ratio`
    }
    if External.OperationType  == "SlidingVertical"
    {   `External.Z Translate` = `External.Panel Height`  * `External.Open Ratio`
    }
  rule "Rotation Rule":
    /*Rule created by alan 9/27/2006*/
    if External.Vertical==true
    {Line36 = Rotate12
    	Line37 =Line35
    Point81 =Rotate11 }
    else
    {Line36 =Line34
    	Line37 =Rotate10
    Point81 =Rotate9 }
  rule "Dimension Rule":
    /*Rule created by alan 9/27/2006*/
    `External.Open Angle` = 0deg
    `External.Rotate Axis Offset` =0ft
    `External.X Translate` = 0ft
    `External.Z Translate` = 0ft
    External.Vertical =true
    if External.OperationType  == "SideHungRightHand"
    {  `External.Rotate Axis Offset`  = `External.Panel Width`
    	`External.Open Angle` =- PI/2*`External.Open Ratio`
    }
    if External.OperationType  == "SideHungLeftHand"
    {   `External.Open Angle` =  PI/2*`External.Open Ratio`
    }
    if External.OperationType  == "TiltAndTurnRightHand"
    {    `External.Rotate Axis Offset`  = `External.Panel Width`
    	`External.Open Angle` = -PI/2*`External.Open Ratio`
    }
    if External.OperationType  == "TiltAndTurnLeftHand"
    {   `External.Open Angle` = PI/2*`External.Open Ratio`
    }
    if External.OperationType  == "TopHung"
    {  `External.Rotate Axis Offset` =`External.Panel Height`
    	`External.Open Angle` = PI/2*`External.Open Ratio`
    	External.Vertical = false
    }
    if External.OperationType  == "BottomHung"
    {   `External.Open Angle` = -PI/2*`External.Open Ratio`
    	External.Vertical = false
    }
    if External.OperationType  == "PivotVertical"
    {   `External.Open Angle` = PI/2*`External.Open Ratio`
    	`External.Rotate Axis Offset` =`External.Panel Width` /2
    }
    if External.OperationType  == "PivotHorizontal"
    {   `External.Open Angle` = PI/2*`External.Open Ratio`
    	`External.Rotate Axis Offset` =`External.Panel Height` /2
    	External.Vertical = false
    }
    if External.OperationType  == "SlidingHorizontal"
    {  `External.X Translate` = `External.Panel Width` * `External.Open Ratio`
    }
    if External.OperationType  == "SlidingVertical"
    {   `External.Z Translate` = `External.Panel Height`  * `External.Open Ratio`
    }
  rule "Rotation Rule":
    /*Rule created by alan 9/27/2006*/
    if External.Vertical==true
    {Line46 = Rotate16
    	Line47 =Line45
    Point106 =Rotate15 }
    else
    {Line46 =Line44
    	Line47 =Rotate14
    Point106 =Rotate13 }
  rule "Dimension Rule":
    /*Rule created by alan 9/27/2006*/
    `External.Open Angle` = 0deg
    `External.Rotate Axis Offset` =0ft
    `External.X Translate` = 0ft
    `External.Z Translate` = 0ft
    External.Vertical =true
    if External.OperationType  == "SideHungRightHand"
    {  `External.Rotate Axis Offset`  = `External.Panel Width`
    	`External.Open Angle` =- PI/2*`External.Open Ratio`
    }
    if External.OperationType  == "SideHungLeftHand"
    {   `External.Open Angle` =  PI/2*`External.Open Ratio`
    }
    if External.OperationType  == "TiltAndTurnRightHand"
    {    `External.Rotate Axis Offset`  = `External.Panel Width`
    	`External.Open Angle` = -PI/2*`External.Open Ratio`
    }
    if External.OperationType  == "TiltAndTurnLeftHand"
    {   `External.Open Angle` = PI/2*`External.Open Ratio`
    }
    if External.OperationType  == "TopHung"
    {  `External.Rotate Axis Offset` =`External.Panel Height`
    	`External.Open Angle` = PI/2*`External.Open Ratio`
    	External.Vertical = false
    }
    if External.OperationType  == "BottomHung"
    {   `External.Open Angle` = -PI/2*`External.Open Ratio`
    	External.Vertical = false
    }
    if External.OperationType  == "PivotVertical"
    {   `External.Open Angle` = PI/2*`External.Open Ratio`
    	`External.Rotate Axis Offset` =`External.Panel Width` /2
    }
    if External.OperationType  == "PivotHorizontal"
    {   `External.Open Angle` = PI/2*`External.Open Ratio`
    	`External.Rotate Axis Offset` =`External.Panel Height` /2
    	External.Vertical = false
    }
    if External.OperationType  == "SlidingHorizontal"
    {  `External.X Translate` = `External.Panel Width` * `External.Open Ratio`
    }
    if External.OperationType  == "SlidingVertical"
    {   `External.Z Translate` = `External.Panel Height`  * `External.Open Ratio`
    }
  rule "Rotation Rule":
    /*Rule created by alan 9/27/2006*/
    if External.Vertical==true
    {Line56 = Rotate20
    	Line57 =Line55
    Point131 =Rotate19 }
    else
    {Line56 =Line54
    	Line57 =Rotate18
    Point131 =Rotate17 }
  `GTCArcWall4.H-Offset` = 0mm
  `GTCArcWall4.V-Offset` = `Sill-Bottom`
  `Sill-Top` = `Sill-Right`
  `Sill-Left` = `Sill-Right`
  `Sill-Right` = `Sill-Bottom`
  `GTCArcWall1.H-Offset` = 0mm
  `GTCArcWall1.V-Offset` = `Sill-Bottom`
  rule "Dimension Rule":
    /*Rule created by alan 9/27/2006*/
    `External.Open Angle` = 0deg
    `External.Rotate Axis Offset` =0ft
    `External.X Translate` = 0ft
    `External.Z Translate` = 0ft
    External.Vertical =true
    if External.OperationType  == "SideHungRightHand"
    {  `External.Rotate Axis Offset`  = `External.Panel Width`
    	`External.Open Angle` =- PI/2*`External.Open Ratio`
    }
    if External.OperationType  == "SideHungLeftHand"
    {   `External.Open Angle` =  PI/2*`External.Open Ratio`
    }
    if External.OperationType  == "TiltAndTurnRightHand"
    {    `External.Rotate Axis Offset`  = `External.Panel Width`
    	`External.Open Angle` = -PI/2*`External.Open Ratio`
    }
    if External.OperationType  == "TiltAndTurnLeftHand"
    {   `External.Open Angle` = PI/2*`External.Open Ratio`
    }
    if External.OperationType  == "TopHung"
    {  `External.Rotate Axis Offset` =`External.Panel Height`
    	`External.Open Angle` = PI/2*`External.Open Ratio`
    	External.Vertical = false
    }
    if External.OperationType  == "BottomHung"
    {   `External.Open Angle` = -PI/2*`External.Open Ratio`
    	External.Vertical = false
    }
    if External.OperationType  == "PivotVertical"
    {   `External.Open Angle` = PI/2*`External.Open Ratio`
    	`External.Rotate Axis Offset` =`External.Panel Width` /2
    }
    if External.OperationType  == "PivotHorizontal"
    {   `External.Open Angle` = PI/2*`External.Open Ratio`
    	`External.Rotate Axis Offset` =`External.Panel Height` /2
    	External.Vertical = false
    }
    if External.OperationType  == "SlidingHorizontal"
    {  `External.X Translate` = `External.Panel Width` * `External.Open Ratio`
    }
    if External.OperationType  == "SlidingVertical"
    {   `External.Z Translate` = `External.Panel Height`  * `External.Open Ratio`
    }
  rule "Rotation Rule":
    /*Rule created by alan 9/27/2006*/
    if External.Vertical==true
    {Line67 = Rotate24
    	Line68 =Line66
    Point159 =Rotate23 }
    else
    {Line67 =Line65
    	Line68 =Rotate22
    Point159 =Rotate21 }
  `Sill-Top` = `Sill-Right`
  `Sill-Left` = `Sill-Right`
  `Sill-Right` = `Sill-Bottom`
  `GTCArcWall1.H-Offset` = 0mm
  `GTCArcWall1.V-Offset` = `Sill-Bottom`
  rule "Dimension Rule":
    /*Rule created by alan 9/27/2006*/
    `External.Open Angle` = 0deg
    `External.Rotate Axis Offset` =0ft
    `External.X Translate` = 0ft
    `External.Z Translate` = 0ft
    External.Vertical =true
    if External.OperationType  == "SideHungRightHand"
    {  `External.Rotate Axis Offset`  = `External.Panel Width`
    	`External.Open Angle` =- PI/2*`External.Open Ratio`
    }
    if External.OperationType  == "SideHungLeftHand"
    {   `External.Open Angle` =  PI/2*`External.Open Ratio`
    }
    if External.OperationType  == "TiltAndTurnRightHand"
    {    `External.Rotate Axis Offset`  = `External.Panel Width`
    	`External.Open Angle` = -PI/2*`External.Open Ratio`
    }
    if External.OperationType  == "TiltAndTurnLeftHand"
    {   `External.Open Angle` = PI/2*`External.Open Ratio`
    }
    if External.OperationType  == "TopHung"
    {  `External.Rotate Axis Offset` =`External.Panel Height`
    	`External.Open Angle` = PI/2*`External.Open Ratio`
    	External.Vertical = false
    }
    if External.OperationType  == "BottomHung"
    {   `External.Open Angle` = -PI/2*`External.Open Ratio`
    	External.Vertical = false
    }
    if External.OperationType  == "PivotVertical"
    {   `External.Open Angle` = PI/2*`External.Open Ratio`
    	`External.Rotate Axis Offset` =`External.Panel Width` /2
    }
    if External.OperationType  == "PivotHorizontal"
    {   `External.Open Angle` = PI/2*`External.Open Ratio`
    	`External.Rotate Axis Offset` =`External.Panel Height` /2
    	External.Vertical = false
    }
    if External.OperationType  == "SlidingHorizontal"
    {  `External.X Translate` = `External.Panel Width` * `External.Open Ratio`
    }
    if External.OperationType  == "SlidingVertical"
    {   `External.Z Translate` = `External.Panel Height`  * `External.Open Ratio`
    }
  rule "Rotation Rule":
    /*Rule created by alan 9/27/2006*/
    if External.Vertical==true
    {Line78 = Rotate28
    	Line79 =Line77
    Point187 =Rotate27 }
    else
    {Line78 =Line76
    	Line79 =Rotate26
    Point187 =Rotate25 }
  `Sill-Top` = `Sill-Right`
  `Sill-Left` = `Sill-Right`
  `Sill-Right` = `Sill-Bottom`
  `GTCArcWall1.H-Offset` = 0mm
  `GTCArcWall1.V-Offset` = `Sill-Bottom`
  rule "Dimension Rule":
    /*Rule created by alan 9/27/2006*/
    `External.Open Angle` = 0deg
    `External.Rotate Axis Offset` =0ft
    `External.X Translate` = 0ft
    `External.Z Translate` = 0ft
    External.Vertical =true
    if External.OperationType  == "SideHungRightHand"
    {  `External.Rotate Axis Offset`  = `External.Panel Width`
    	`External.Open Angle` =- PI/2*`External.Open Ratio`
    }
    if External.OperationType  == "SideHungLeftHand"
    {   `External.Open Angle` =  PI/2*`External.Open Ratio`
    }
    if External.OperationType  == "TiltAndTurnRightHand"
    {    `External.Rotate Axis Offset`  = `External.Panel Width`
    	`External.Open Angle` = -PI/2*`External.Open Ratio`
    }
    if External.OperationType  == "TiltAndTurnLeftHand"
    {   `External.Open Angle` = PI/2*`External.Open Ratio`
    }
    if External.OperationType  == "TopHung"
    {  `External.Rotate Axis Offset` =`External.Panel Height`
    	`External.Open Angle` = PI/2*`External.Open Ratio`
    	External.Vertical = false
    }
    if External.OperationType  == "BottomHung"
    {   `External.Open Angle` = -PI/2*`External.Open Ratio`
    	External.Vertical = false
    }
    if External.OperationType  == "PivotVertical"
    {   `External.Open Angle` = PI/2*`External.Open Ratio`
    	`External.Rotate Axis Offset` =`External.Panel Width` /2
    }
    if External.OperationType  == "PivotHorizontal"
    {   `External.Open Angle` = PI/2*`External.Open Ratio`
    	`External.Rotate Axis Offset` =`External.Panel Height` /2
    	External.Vertical = false
    }
    if External.OperationType  == "SlidingHorizontal"
    {  `External.X Translate` = `External.Panel Width` * `External.Open Ratio`
    }
    if External.OperationType  == "SlidingVertical"
    {   `External.Z Translate` = `External.Panel Height`  * `External.Open Ratio`
    }
  rule "Rotation Rule":
    /*Rule created by alan 9/27/2006*/
    if External.Vertical==true
    {Line89 = Rotate32
    	Line90 =Line88
    Point215 =Rotate31 }
    else
    {Line89 =Line87
    	Line90 =Rotate30
    Point215 =Rotate29 }
  `Sill-Top` = `Sill-Right`
  `Sill-Left` = `Sill-Right`
  `Sill-Right` = `Sill-Bottom`
  `GTCArcWall1.H-Offset` = 0mm
  `GTCArcWall1.V-Offset` = `Sill-Bottom`
  rule "Dimension Rule":
    /*Rule created by alan 9/27/2006*/
    `External.Open Angle` = 0deg
    `External.Rotate Axis Offset` =0ft
    `External.X Translate` = 0ft
    `External.Z Translate` = 0ft
    External.Vertical =true
    if External.OperationType  == "SideHungRightHand"
    {  `External.Rotate Axis Offset`  = `External.Panel Width`
    	`External.Open Angle` =- PI/2*`External.Open Ratio`
    }
    if External.OperationType  == "SideHungLeftHand"
    {   `External.Open Angle` =  PI/2*`External.Open Ratio`
    }
    if External.OperationType  == "TiltAndTurnRightHand"
    {    `External.Rotate Axis Offset`  = `External.Panel Width`
    	`External.Open Angle` = -PI/2*`External.Open Ratio`
    }
    if External.OperationType  == "TiltAndTurnLeftHand"
    {   `External.Open Angle` = PI/2*`External.Open Ratio`
    }
    if External.OperationType  == "TopHung"
    {  `External.Rotate Axis Offset` =`External.Panel Height`
    	`External.Open Angle` = PI/2*`External.Open Ratio`
    	External.Vertical = false
    }
    if External.OperationType  == "BottomHung"
    {   `External.Open Angle` = -PI/2*`External.Open Ratio`
    	External.Vertical = false
    }
    if External.OperationType  == "PivotVertical"
    {   `External.Open Angle` = PI/2*`External.Open Ratio`
    	`External.Rotate Axis Offset` =`External.Panel Width` /2
    }
    if External.OperationType  == "PivotHorizontal"
    {   `External.Open Angle` = PI/2*`External.Open Ratio`
    	`External.Rotate Axis Offset` =`External.Panel Height` /2
    	External.Vertical = false
    }
    if External.OperationType  == "SlidingHorizontal"
    {  `External.X Translate` = `External.Panel Width` * `External.Open Ratio`
    }
    if External.OperationType  == "SlidingVertical"
    {   `External.Z Translate` = `External.Panel Height`  * `External.Open Ratio`
    }
  rule "Rotation Rule":
    /*Rule created by alan 9/27/2006*/
    if External.Vertical==true
    {Line100 = Rotate36
    	Line101 =Line99
    Point243 =Rotate35 }
    else
    {Line100 =Line98
    	Line101 =Rotate34
    Point243 =Rotate33 }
